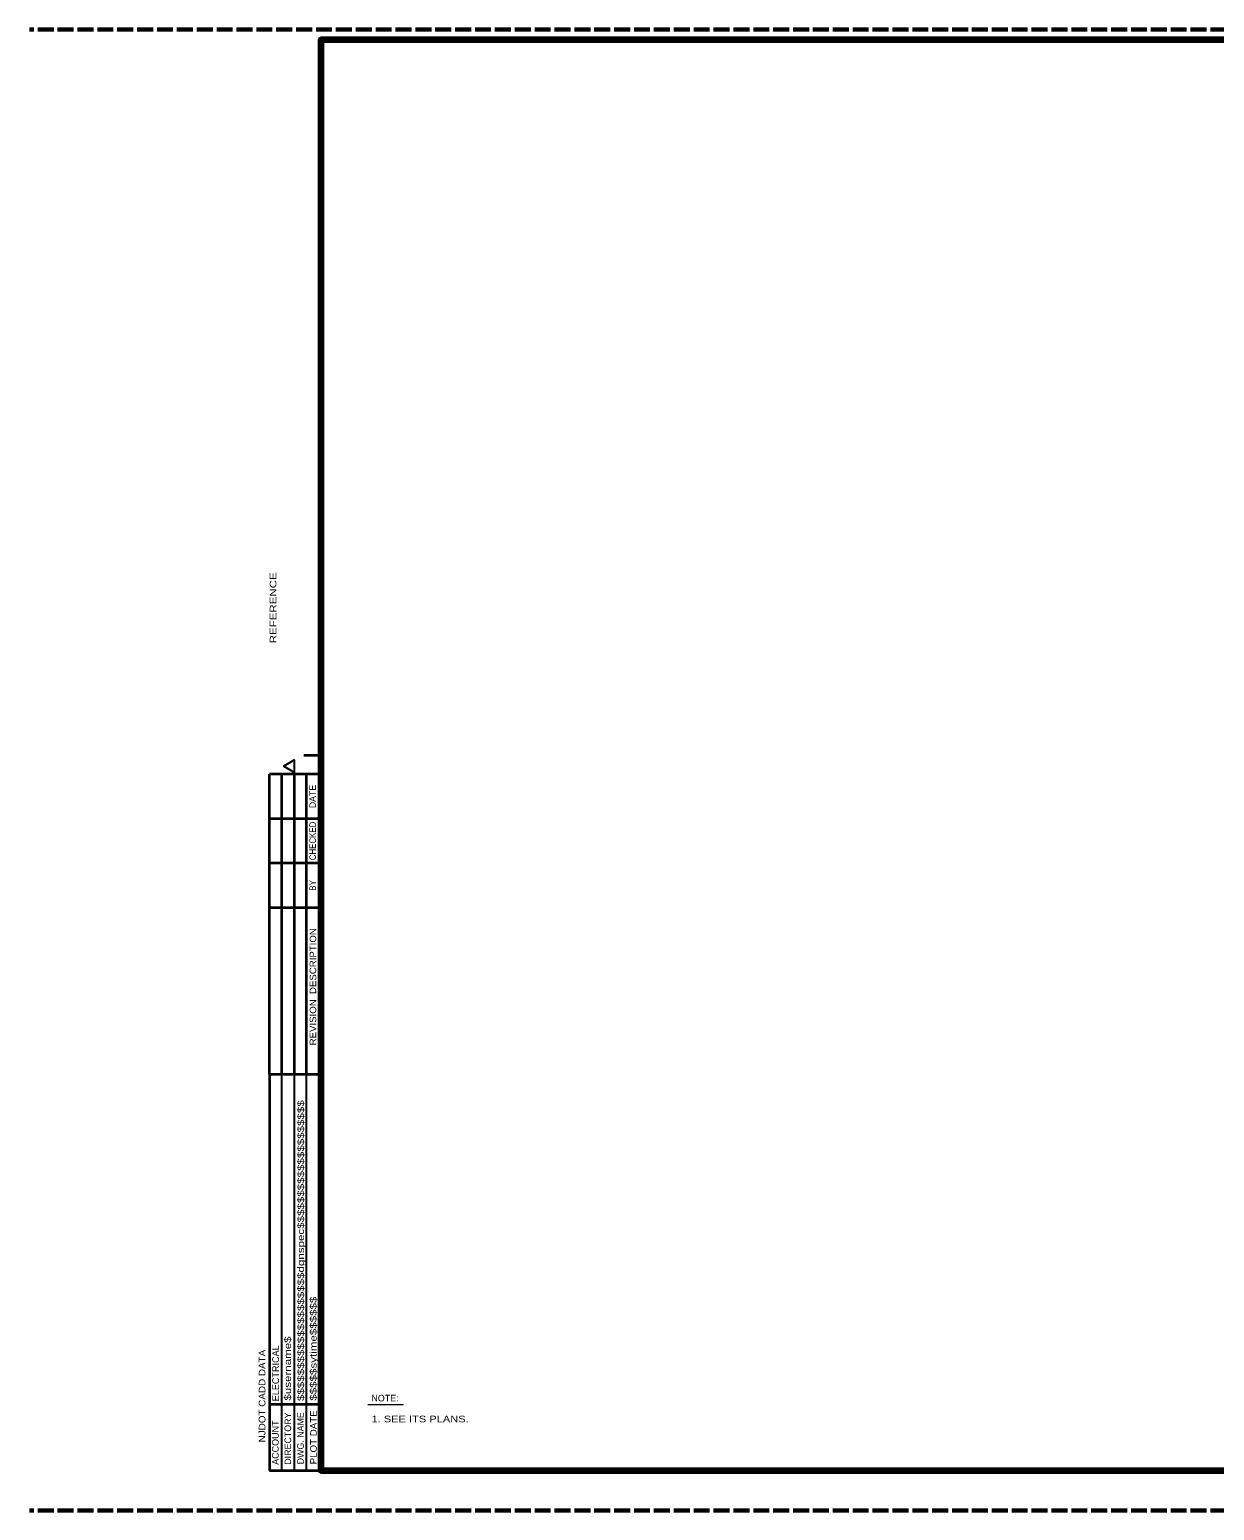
# Model space of a CAD drawing. Extents: x 168423 to 169396, y 223543 to 223937.
# Drawn here: x 169127.8 to 169261.9, y 223542.6 to 223710.3 of the extents above; entities that cross this region are included whole.
import ezdxf
from ezdxf.enums import TextEntityAlignment as Align

# ---------------------------------------------------------------- set-up
doc = ezdxf.new("R2010")
doc.units = 0
doc.header["$LTSCALE"] = 0.3
doc.linetypes.add('LONG_DASHED', pattern=[7.5, 6, -1.5])
for name, color, linetype, lineweight in [('1', 7, 'Continuous', 13), ('12', 7, 'Continuous', 13), ('25', 7, 'Continuous', 35)]:
    doc.layers.add(name, color=color, linetype=linetype, lineweight=lineweight)

msp = doc.modelspace()

# ---------------------------------------------------------------- linework, layer by layer
at = {"layer": '1', "linetype": 'LONG_DASHED', "lineweight": 60}
for p, q in [((169396.0594, 223710.2685), (169127.8354, 223710.2685)), ((169396.0594, 223542.6285), (169127.8354, 223542.6285))]:
    msp.add_line(p, q, dxfattribs=at)
at = {"layer": '1', "lineweight": 35}
for p, q in [((169158.8894, 223628.1285), (169160.8094, 223628.1285)), ((169154.9721, 223592.02), (169160.8094, 223592.02)), ((169154.9721, 223592.02), (169154.9721, 223547.1285)), ((169154.9721, 223554.6646), (169160.8094, 223554.6646)), ((169154.9721, 223547.1285), (169160.8094, 223547.1285))]:
    msp.add_line(p, q, dxfattribs=at)
at = {"layer": '1', "lineweight": 25}
for p, q in [((169156.3907, 223547.1285), (169156.3907, 223592.02)), ((169157.8094, 223547.1285), (169157.8094, 223592.02)), ((169159.1919, 223547.1285), (169159.1919, 223592.02))]:
    msp.add_line(p, q, dxfattribs=at)
at = {"layer": '1', "lineweight": 158}
msp.add_lwpolyline([(169393.3094, 223547.1285), (169393.3094, 223709.1285), (169160.8094, 223709.1285), (169160.8094, 223547.1285)], close=True, dxfattribs=at)
at = {"layer": '12'}
msp.add_line((169166.1333, 223554.621), (169170.1706, 223554.621), dxfattribs=at)
at = {"layer": '25'}
for p, q in [((169160.8094, 223625.9598), (169154.9721, 223625.9598)), ((169154.9721, 223592.02), (169154.9721, 223625.9598)), ((169156.3907, 223592.02), (169156.3907, 223625.9598)), ((169157.8094, 223592.02), (169157.8094, 223625.9598)), ((169159.1919, 223592.02), (169159.1919, 223625.9598)), ((169160.8094, 223620.9267), (169154.9721, 223620.9267)), ((169160.8094, 223615.8935), (169154.9721, 223615.8935)), ((169160.8094, 223610.8604), (169154.9721, 223610.8604)), ((169160.6106, 223610.8604), (169159.1919, 223610.8604))]:
    msp.add_line(p, q, dxfattribs=at)
at = {"layer": '25', "lineweight": 25}
msp.add_lwpolyline([(169157.8184, 223627.5863), (169156.5986, 223626.8815), (169157.8184, 223626.1767)], close=True, dxfattribs=at)

# ---------------------------------------------------------------- texts
at = {"layer": '1'}
for s, height, width, p in [('REFERENCE                                                              ', 0.75, 1.3, (169155.7694, 223640.7885)), ('$$$$$$$$$$$$$$$$$$$$dgnspec$$$$$$$$$$$$$$$$$$$$', 0.7526, 1.3, (169158.9028, 223555.008)), ('$$$$$sytime$$$$$$', 0.7526, 1.3, (169160.3214, 223555.0442)), ('$username$', 0.7526, 1.3, (169157.4208, 223555.0532)), ('NJDOT CADD DATA', 0.759, 1.1, (169154.5293, 223550.3273)), ('PLOT DATE', 0.7499, 1.1, (169160.3395, 223547.8333))]:
    msp.add_text(s, height=height, rotation=90, dxfattribs=dict(at, width=width)).set_placement(p)
for s, height, p in [('ELECTRICAL', 0.768, (169156.0654, 223554.9809)), ('DIRECTORY', 0.75, (169157.4389, 223547.7972)), ('DWG. NAME', 0.75, (169158.8757, 223547.8424)), ('ACCOUNT', 0.7589, (169156.0293, 223547.7881))]:
    msp.add_text(s, height=height, rotation=90, dxfattribs=at).set_placement(p)
at = {"layer": '12'}
msp.add_text('NOTE:', height=0.75, dxfattribs=at).set_placement((169166.5321, 223554.9647))
at = {"layer": '12', "width": 1.25}
msp.add_text('1. SEE ITS PLANS.', height=0.75, dxfattribs=at).set_placement((169166.5321, 223552.5986))
at = {"layer": '25'}
msp.add_text('DATE', height=0.741, rotation=90, dxfattribs=at).set_placement((169160.2401, 223623.4498), align=Align.CENTER)
for s, width, p in [('CHECKED', 0.9, (169160.2401, 223618.416)), ('BY', 0.9, (169160.2401, 223613.3795)), ('REVISION  DESCRIPTION', 1.1, (169160.2763, 223601.9087))]:
    msp.add_text(s, height=0.741, rotation=90, dxfattribs=dict(at, width=width)).set_placement(p, align=Align.CENTER)

doc.saveas('drawing.dxf')
